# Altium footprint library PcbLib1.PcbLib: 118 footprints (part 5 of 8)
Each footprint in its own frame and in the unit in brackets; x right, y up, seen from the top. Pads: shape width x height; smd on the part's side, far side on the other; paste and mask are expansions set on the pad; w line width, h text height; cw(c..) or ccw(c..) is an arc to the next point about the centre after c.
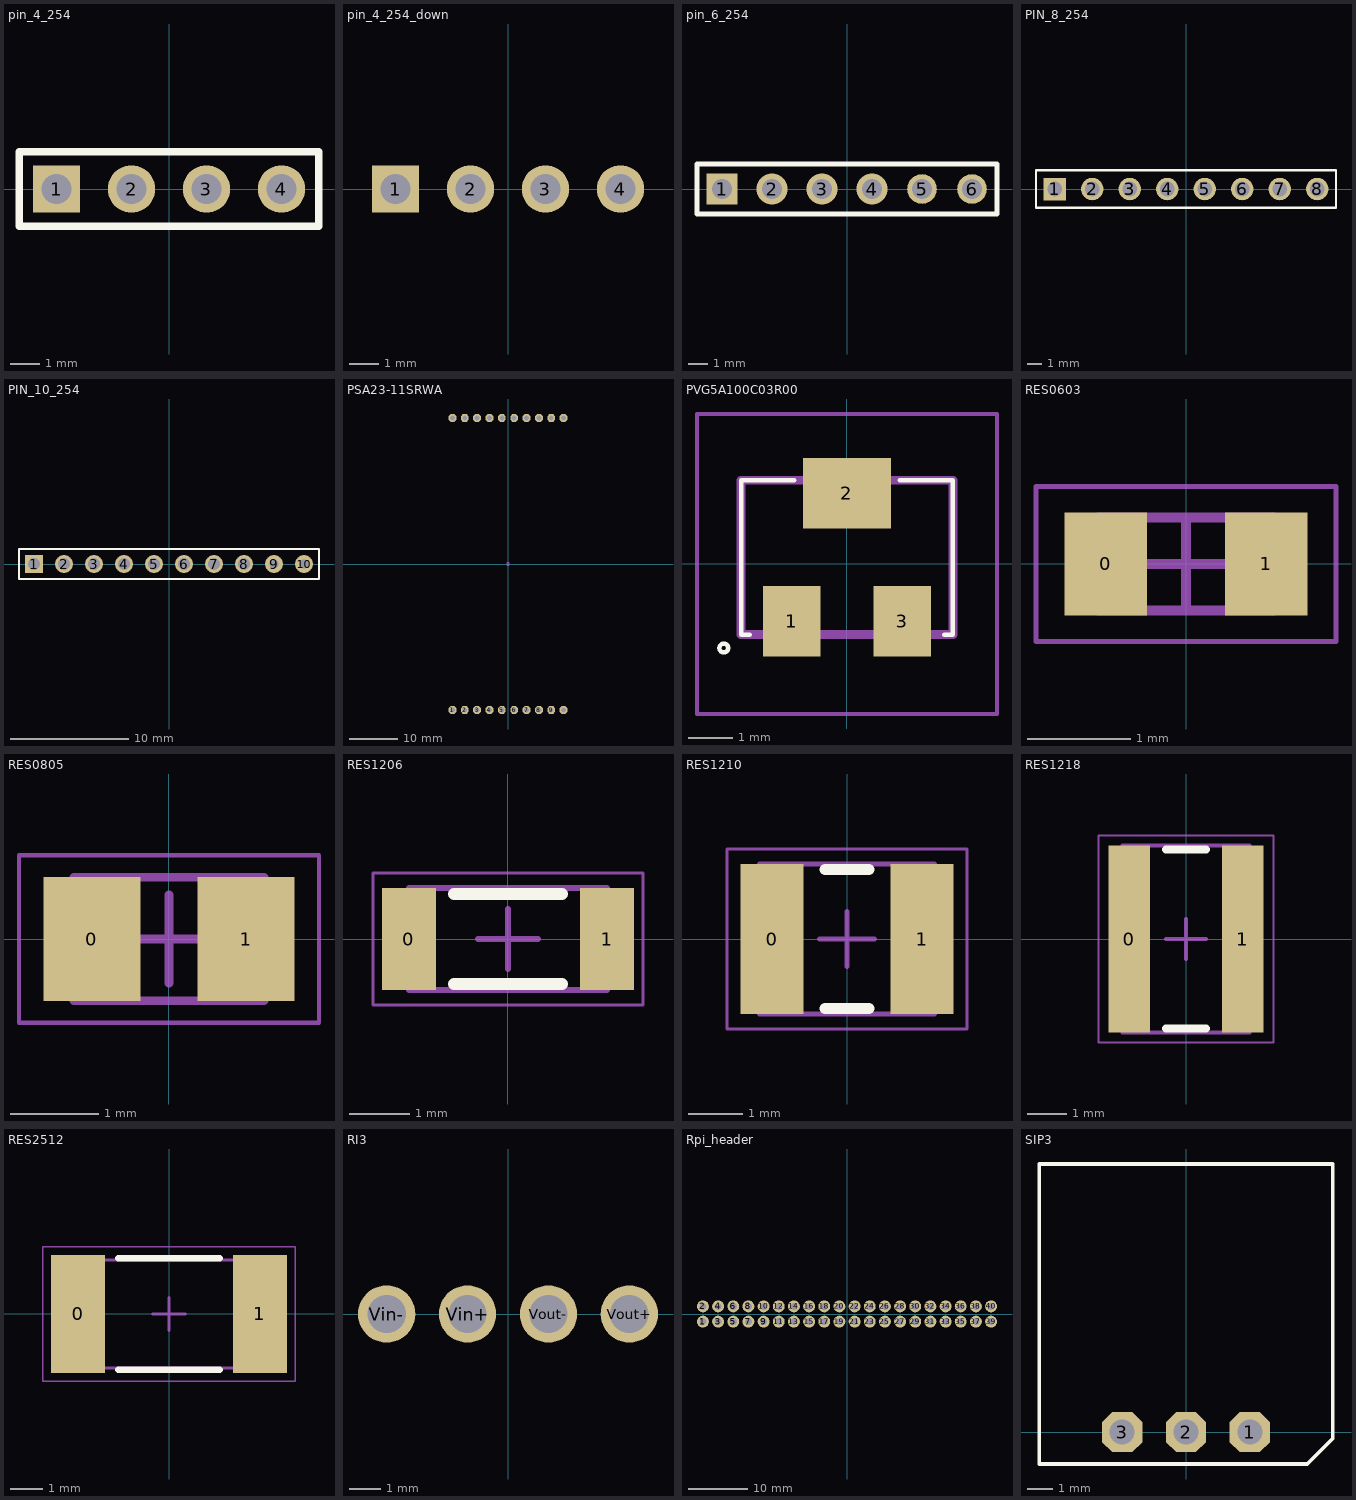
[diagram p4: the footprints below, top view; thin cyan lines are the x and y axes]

## pin_4_254 [mm]
pads (4):
  rect 1.6x1.6 hole 1: 1(-3.81,0)
  round 1.6 hole 1: 2(-1.27,0) 3(1.27,0) 4(3.81,0)
Top Overlay:
  lines w0.254: -5.08,-1.27 5.08,-1.27 5.08,1.27 -5.08,1.27 -5.08,-1.27
3D body "header_4.STEP": height 8.6, standoff -3, extent -5.08,-1.27 5.08,1.27

## pin_4_254_down [mm]
pads (4):
  rect 1.6x1.6 hole 1: 1(-3.81,0)
  round 1.6 hole 1: 2(-1.27,0) 3(1.27,0) 4(3.81,0)
Bottom Overlay:
  lines w0.254: -5.08,-1.27 5.08,-1.27 5.08,1.27 -5.08,1.27 -5.08,-1.27
3D body "header_4.STEP": height 2.55, standoff -9.05, extent -5.08,-1.27 5.08,1.27

## pin_6_254 [mm]
pads (6):
  rect 1.6x1.6 hole 1: 1(-6.35,0)
  round 1.6 hole 1: 2(-3.81,0) 3(-1.27,0) 4(1.27,0)
  round 1.5 hole 1 unplated: 5(3.81,0) 6(6.35,0)
Top Overlay:
  lines w0.254: -7.62,-1.27 7.62,-1.27 7.62,1.27 -7.62,1.27 -7.62,-1.27

## PIN_8_254 [mil]
pads (8):
  rect 60x60 hole 39.37: 1(-350,0)
  round 60 hole 39.37: 2(-250,0) 3(-150,0) 4(-50,0) 5(50,0) 6(150,0) 7(250,0) 8(350,0)
Top Overlay:
  lines w5.91: -400,-50 -400,50 400,50 400,-50 -400,-50

## PIN_10_254 [mil]
pads (10):
  rect 60x60 hole 39.37: 1(-450,0)
  round 60 hole 39.37: 2(-350,0) 3(-250,0) 4(-150,0) 5(-50,0) 6(50,0) 7(150,0) 8(250,0)
  round 60 hole 30: 9(350,0) 10(450,0)
Top Overlay:
  lines w5.91: -500,-50 -500,50 500,50 500,-50 -500,-50

## PSA23-11SRWA [mm] "16 seg display"
pads (20):
  oct 1.6x1.6 hole 1: 1(-11.43,-30.05) 2(-8.89,-30.05) 3(-6.35,-30.05) 4(-3.81,-30.05) 5(-1.27,-30.05) 6(1.27,-30.05) 7(3.81,-30.05) 8(6.35,-30.05) 9(8.89,-30.05) 10(11.43,-30.05) 11(11.43,30.05) 12(8.89,30.05) 13(6.35,30.05) 14(3.81,30.05) 15(1.27,30.05) 16(-1.27,30.05) 17(-3.81,30.05) 18(-6.35,30.05) 19(-8.89,30.05) 20(-11.43,30.05)
Mechanical 20:
  circle w0.1: c0,0 r0.254
3D body "PSA23-11SRWA.STEP": height 10, standoff -4, extent -23.9,-34.915 23.9,34.925

## PVG5A100C03R00 [mm]
pads (3):
  rect 1.3x1.6 smd: 1(-1.25,-1.3) 3(1.25,-1.3)
  rect 2x1.6 smd: 2(0,1.6)
Top Overlay:
  circle w0.1: c-2.794,-1.905 r0.1
  lines w0.1: -2.2,-1.6 -2.4,-1.6 -2.4,1.9 -1.2,1.9 ; 1.2,1.9 2.4,1.9 2.4,-1.6 2.2,-1.6
Mechanical 15:
  lines w0.2: -2.4,-1.6 -2.4,1.9 2.4,1.9 2.4,-1.6 -2.4,-1.6
Mechanical 20:
  lines w0.1: -3.4,-3.4 -3.4,3.4 3.4,3.4 3.4,-3.4 -3.4,-3.4
3D body "PVG5A.STEP": height 5.3, standoff 0, extent -2.375,-1.702 2.425,1.998

## RES0603 [mm]
height 0.55
pads (2):
  rect 0.8x1 smd: 0(-0.775,0) 1(0.775,0)
Mechanical 13:
  lines w0.1: -0.85,-0.45 0.85,-0.45 0.85,0.45 -0.85,0.45 -0.85,-0.45
Mechanical 15:
  lines w0.05: -1.45,-0.75 1.45,-0.75 1.45,0.75 -1.45,0.75 -1.45,-0.75
  lines w0.1: -0.45,0 0.45,0 ; 0,-0.45 0,0.45
3D body "RES0603.step": height 0.55, standoff 0, extent -0.85,-0.45 0.85,0.45

## RES0805 [mm]
height 0.65
pads (2):
  rect 1.1x1.4 smd: 0(-0.875,0) 1(0.875,0)
Mechanical 13:
  lines w0.1: -1.075,-0.7 1.075,-0.7 1.075,0.7 -1.075,0.7 -1.075,-0.7
Mechanical 15:
  lines w0.05: -1.7,-0.95 1.7,-0.95 1.7,0.95 -1.7,0.95 -1.7,-0.95
  lines w0.1: -0.5,0 0.5,0 ; 0,-0.5 0,0.5
3D body "RES0805.step": height 0.65, standoff 0, extent -1.075,-0.7 1.075,0.7

## RES1206 [mm] "Chip Resistor, 2-Leads, Body 3,15x1,60mm, IPC Medium Density"
height 0.55
pads (2):
  rect 0.9x1.7 smd: 0(-1.65,0) 1(1.65,0)
Top Overlay:
  lines w0.2: -0.9,-0.75 0.9,-0.75 ; -0.9,0.75 0.9,0.75
Mechanical 13:
  lines w0.1: -1.65,-0.85 1.65,-0.85 1.65,0.85 -1.65,0.85 -1.65,-0.85
Mechanical 15:
  lines w0.05: -2.25,-1.1 2.25,-1.1 2.25,1.1 -2.25,1.1 -2.25,-1.1
  lines w0.1: -0.5,0 0.5,0 ; 0,-0.5 0,0.5
3D body "RES1206.step": height 0.55, standoff 0, extent -1.65,-0.85 1.65,0.85

## RES1210 [mm]
height 0.65
pads (2):
  rect 1.15x2.75 smd: 0(-1.375,0) 1(1.375,0)
Top Overlay:
  lines w0.2: -0.4,-1.275 0.4,-1.275 ; -0.4,1.275 0.4,1.275
Mechanical 13:
  lines w0.1: -1.6,-1.375 -1.6,1.375 1.6,1.375 1.6,-1.375 -1.6,-1.375
Mechanical 15:
  lines w0.05: -2.2,-1.65 -2.2,1.65 2.2,1.65 2.2,-1.65 -2.2,-1.65
  lines w0.1: -0.5,0 0.5,0 ; 0,-0.5 0,0.5
3D body "RES1210.step": height 0.65, standoff 0, extent -1.6,-1.375 1.6,1.375

## RES1218 [mm]
height 0.65
pads (2):
  rect 1.05x4.7 smd: 0(-1.425,0) 1(1.425,0)
Top Overlay:
  lines w0.2: -0.5,-2.25 0.5,-2.25 ; -0.5,2.25 0.5,2.25
Mechanical 13:
  lines w0.1: -1.6,-2.35 1.6,-2.35 1.6,2.35 -1.6,2.35 -1.6,-2.35
Mechanical 15:
  lines w0.05: -2.2,-2.6 2.2,-2.6 2.2,2.6 -2.2,2.6 -2.2,-2.6
  lines w0.1: -0.5,0 0.5,0 ; 0,-0.5 0,0.5
3D body "RES1218.step": height 0.65, standoff 0, extent -1.6,-2.35 1.6,2.35

## RES2512 [mm]
height 0.7
pads (2):
  rect 1.65x3.6 smd: 0(-2.775,0) 1(2.775,0)
Top Overlay:
  lines w0.2: -1.55,-1.7 1.55,-1.7 ; -1.55,1.7 1.55,1.7
Mechanical 13:
  lines w0.1: -3.25,-1.65 3.25,-1.65 3.25,1.65 -3.25,1.65 -3.25,-1.65
Mechanical 15:
  lines w0.05: -3.85,-2.05 3.85,-2.05 3.85,2.05 -3.85,2.05 -3.85,-2.05
  lines w0.1: -0.5,0 0.5,0 ; 0,-0.5 0,0.5
3D body "RES2512.step": height 0.7, standoff 0, extent -3.25,-1.65 3.25,1.65

## RI3 [mm]
pads (4):
  round 1.8 hole 1.2 mask+0.05: Vin+(-1.27,0) Vin-(-3.81,0) Vout+(3.81,0) Vout-(1.27,0)
3D body "RI3-0505S.STEP": height 10.1, standoff -2.9, extent -5.75,-1.222 5.75,4.778

## Rpi_header [mm]
pads (40):
  round 2 hole 1.2 mask+0.05: 1(-24.13,-1.27) 2(-24.13,1.27) 3(-21.59,-1.27) 4(-21.59,1.27) 5(-19.05,-1.27) 6(-19.05,1.27) 7(-16.51,-1.27) 8(-16.51,1.27) 9(-13.97,-1.27) 10(-13.97,1.27) 11(-11.43,-1.27) 12(-11.43,1.27) 13(-8.89,-1.27) 14(-8.89,1.27) 15(-6.35,-1.27) 16(-6.35,1.27) 17(-3.81,-1.27) 18(-3.81,1.27) 19(-1.27,-1.27) 20(-1.27,1.27) 21(1.27,-1.27) 22(1.27,1.27) 23(3.81,-1.27) 24(3.81,1.27) 25(6.35,-1.27) 26(6.35,1.27) 27(8.89,-1.27) 28(8.89,1.27) 29(11.43,-1.27) 30(11.43,1.27) 31(13.97,-1.27) 32(13.97,1.27) 33(16.51,-1.27) 34(16.51,1.27) 35(19.05,-1.27) 36(19.05,1.27) 37(21.59,-1.27) 38(21.59,1.27) 39(24.13,-1.27) 40(24.13,1.27)

## SIP3 [mm]
pads (3):
  oct 1.6x1.6 hole 1: 1(2.54,0) 2(0,0) 3(-2.54,0)
Top Overlay:
  lines w0.15: -5.842,-1.27 4.826,-1.27 5.842,-0.254 5.842,10.668 -5.842,10.668 -5.842,-1.27
3D body "SIP3_90deg.STEP": height 8.5, standoff -1.35, extent -5.8,-0.35 5.8,10.69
